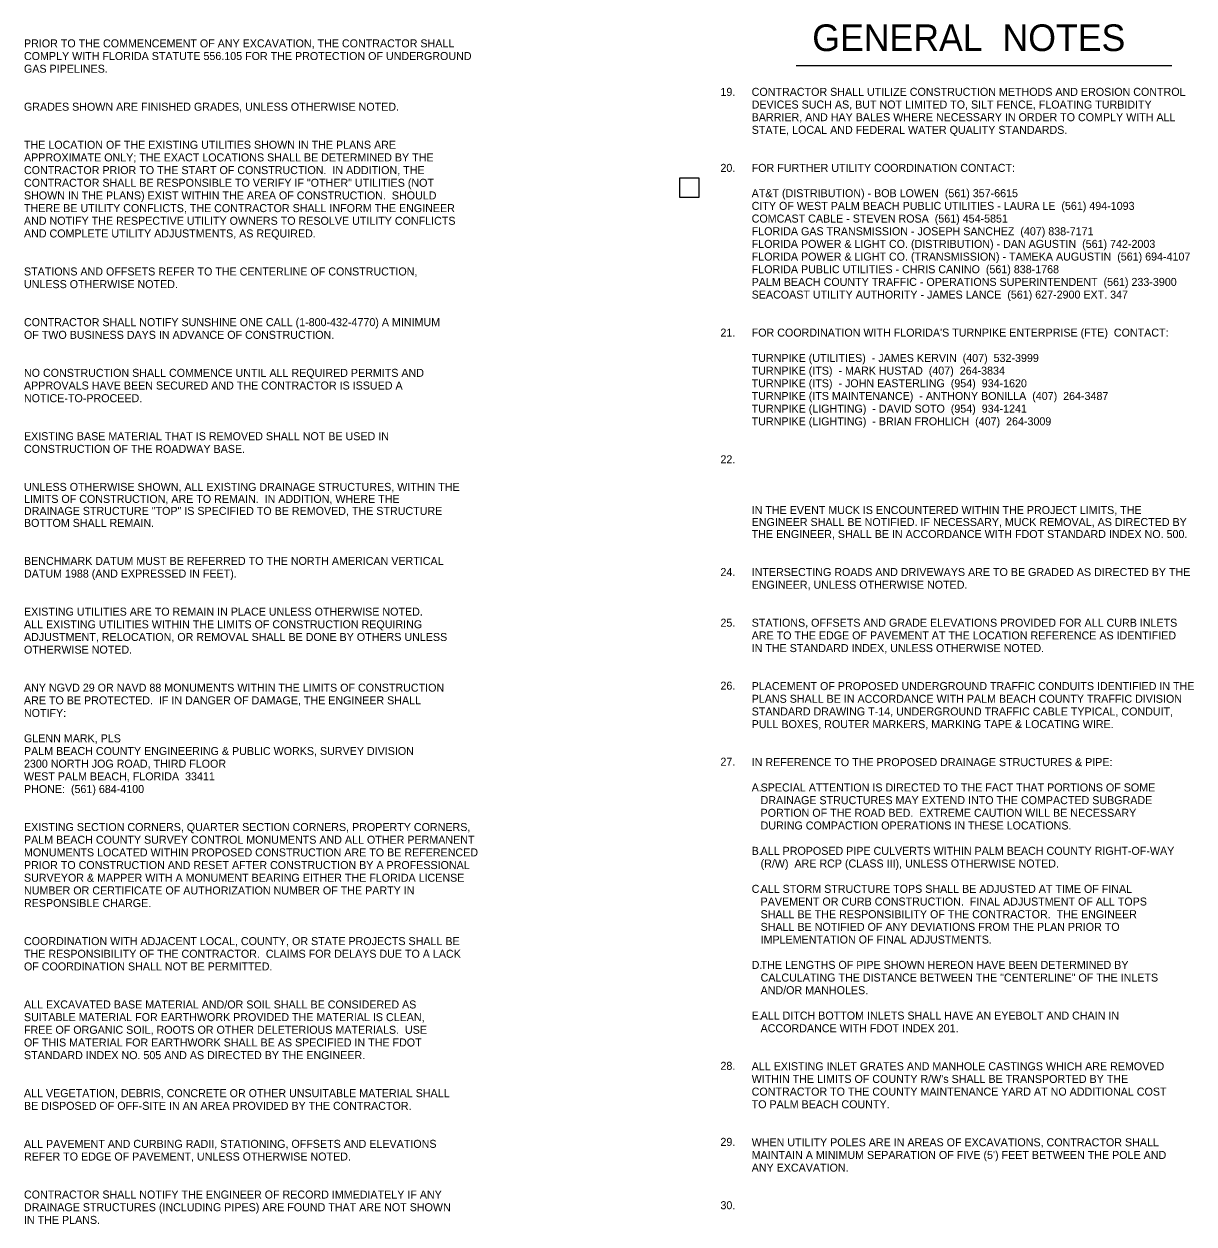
# Model space of a CAD drawing. Extents: x 783907 to 784590, y 832093 to 832609.
# Drawn here: x 784196.7 to 784284.5, y 832519 to 832609 of the extents above; entities that cross this region are included whole.
import ezdxf

# ---------------------------------------------------------------- set-up
doc = ezdxf.new("R2010")
doc.units = 0
doc.layers.add('Default', color=7, linetype='Continuous')

msp = doc.modelspace()

# ---------------------------------------------------------------- linework, layer by layer
at = {"layer": 'Default'}
msp.add_line((784254.603, 832605.859), (784282.795, 832605.859), dxfattribs=at)
msp.add_lwpolyline([(784245.898, 832597.448), (784247.319, 832597.448), (784247.319, 832595.971), (784245.898, 832595.971)], close=True, dxfattribs=at)

# ---------------------------------------------------------------- texts
for s, height, p in [('GENERAL  NOTES', 2, (784255.817, 832606.943)), ('PRIOR TO THE COMMENCEMENT OF ANY EXCAVATION, THE CONTRACTOR SHALL ', 0.6, (784196.695, 832607.22)), ('COMPLY WITH FLORIDA STATUTE 556.105 FOR THE PROTECTION OF UNDERGROUND', 0.6, (784196.695, 832606.27)), ('GAS PIPELINES.', 0.6, (784196.695, 832605.32)), ('19.', 0.6, (784248.932, 832603.587)), ('CONTRACTOR SHALL UTILIZE CONSTRUCTION METHODS AND EROSION CONTROL', 0.6, (784251.275, 832603.587)), ('GRADES SHOWN ARE FINISHED GRADES, UNLESS OTHERWISE NOTED.', 0.6, (784196.695, 832602.47)), ('DEVICES SUCH AS, BUT NOT LIMITED TO, SILT FENCE, FLOATING TURBIDITY', 0.6, (784251.275, 832602.637)), ('BARRIER, AND HAY BALES WHERE NECESSARY IN ORDER TO COMPLY WITH ALL', 0.6, (784251.275, 832601.687)), ('STATE, LOCAL AND FEDERAL WATER QUALITY STANDARDS.', 0.6, (784251.275, 832600.737)), ('THE LOCATION OF THE EXISTING UTILITIES SHOWN IN THE PLANS ARE', 0.6, (784196.695, 832599.62)), ('APPROXIMATE ONLY; THE EXACT LOCATIONS SHALL BE DETERMINED BY THE', 0.6, (784196.695, 832598.67)), ('CONTRACTOR PRIOR TO THE START OF CONSTRUCTION.  IN ADDITION, THE', 0.6, (784196.695, 832597.72)), ('20.', 0.6, (784248.932, 832597.887)), ('FOR FURTHER UTILITY COORDINATION CONTACT:', 0.6, (784251.275, 832597.887)), ('CONTRACTOR SHALL BE RESPONSIBLE TO VERIFY IF "OTHER" UTILITIES (NOT', 0.6, (784196.695, 832596.77)), ('SHOWN IN THE PLANS) EXIST WITHIN THE AREA OF CONSTRUCTION.  SHOULD', 0.6, (784196.695, 832595.82)), ('AT&T (DISTRIBUTION) - BOB LOWEN  (561) 357-6615 ', 0.6, (784251.275, 832595.987)), ('THERE BE UTILITY CONFLICTS, THE CONTRACTOR SHALL INFORM THE ENGINEER', 0.6, (784196.695, 832594.87)), ('CITY OF WEST PALM BEACH PUBLIC UTILITIES - LAURA LE  (561) 494-1093 ', 0.6, (784251.275, 832595.037)), ('AND NOTIFY THE RESPECTIVE UTILITY OWNERS TO RESOLVE UTILITY CONFLICTS', 0.6, (784196.695, 832593.92)), ('COMCAST CABLE - STEVEN ROSA  (561) 454-5851', 0.6, (784251.275, 832594.087)), ('AND COMPLETE UTILITY ADJUSTMENTS, AS REQUIRED.', 0.6, (784196.695, 832592.97)), ('FLORIDA GAS TRANSMISSION - JOSEPH SANCHEZ  (407) 838-7171', 0.6, (784251.275, 832593.137)), ('FLORIDA POWER & LIGHT CO. (DISTRIBUTION) - DAN AGUSTIN  (561) 742-2003', 0.6, (784251.275, 832592.187)), ('FLORIDA POWER & LIGHT CO. (TRANSMISSION) - TAMEKA AUGUSTIN  (561) 694-4107', 0.6, (784251.275, 832591.237)), ('STATIONS AND OFFSETS REFER TO THE CENTERLINE OF CONSTRUCTION,', 0.6, (784196.695, 832590.12)), ('FLORIDA PUBLIC UTILITIES - CHRIS CANINO  (561) 838-1768', 0.6, (784251.275, 832590.287)), ('UNLESS OTHERWISE NOTED.', 0.6, (784196.695, 832589.17)), ('PALM BEACH COUNTY TRAFFIC - OPERATIONS SUPERINTENDENT  (561) 233-3900', 0.6, (784251.275, 832589.337)), ('SEACOAST UTILITY AUTHORITY - JAMES LANCE  (561) 627-2900 EXT. 347', 0.6, (784251.275, 832588.387)), ('CONTRACTOR SHALL NOTIFY SUNSHINE ONE CALL (1-800-432-4770) A MINIMUM', 0.6, (784196.695, 832586.32)), ('OF TWO BUSINESS DAYS IN ADVANCE OF CONSTRUCTION.', 0.6, (784196.695, 832585.37)), ('21.', 0.6, (784248.932, 832585.537)), ("FOR COORDINATION WITH FLORIDA'S TURNPIKE ENTERPRISE (FTE)  CONTACT:", 0.6, (784251.275, 832585.537)), ('TURNPIKE (UTILITIES)  - JAMES KERVIN  (407)  532-3999', 0.6, (784251.275, 832583.637)), ('TURNPIKE (ITS)  - MARK HUSTAD  (407)  264-3834', 0.6, (784251.275, 832582.687)), ('NO CONSTRUCTION SHALL COMMENCE UNTIL ALL REQUIRED PERMITS AND ', 0.6, (784196.695, 832582.52)), ('TURNPIKE (ITS)  - JOHN EASTERLING  (954)  934-1620', 0.6, (784251.275, 832581.737)), ('APPROVALS HAVE BEEN SECURED AND THE CONTRACTOR IS ISSUED A', 0.6, (784196.695, 832581.57)), ('NOTICE-TO-PROCEED.', 0.6, (784196.695, 832580.62)), ('TURNPIKE (ITS MAINTENANCE)  - ANTHONY BONILLA  (407)  264-3487', 0.6, (784251.275, 832580.787)), ('TURNPIKE (LIGHTING)  - DAVID SOTO  (954)  934-1241', 0.6, (784251.275, 832579.837)), ('TURNPIKE (LIGHTING)  - BRIAN FROHLICH  (407)  264-3009', 0.6, (784251.275, 832578.887)), ('EXISTING BASE MATERIAL THAT IS REMOVED SHALL NOT BE USED IN', 0.6, (784196.695, 832577.77)), ('CONSTRUCTION OF THE ROADWAY BASE.', 0.6, (784196.695, 832576.82)), ('22.', 0.6, (784248.932, 832576.037)), ('UNLESS OTHERWISE SHOWN, ALL EXISTING DRAINAGE STRUCTURES, WITHIN THE', 0.6, (784196.695, 832573.97)), ('LIMITS OF CONSTRUCTION, ARE TO REMAIN.  IN ADDITION, WHERE THE', 0.6, (784196.695, 832573.07)), ('DRAINAGE STRUCTURE "TOP" IS SPECIFIED TO BE REMOVED, THE STRUCTURE', 0.6, (784196.695, 832572.17)), ('IN THE EVENT MUCK IS ENCOUNTERED WITHIN THE PROJECT LIMITS, THE', 0.6, (784251.275, 832572.237)), ('BOTTOM SHALL REMAIN.', 0.6, (784196.695, 832571.27)), ('ENGINEER SHALL BE NOTIFIED. IF NECESSARY, MUCK REMOVAL, AS DIRECTED BY', 0.6, (784251.275, 832571.337)), ('THE ENGINEER, SHALL BE IN ACCORDANCE WITH FDOT STANDARD INDEX NO. 500. ', 0.6, (784251.275, 832570.437)), ('BENCHMARK DATUM MUST BE REFERRED TO THE NORTH AMERICAN VERTICAL', 0.6, (784196.695, 832568.42)), ('DATUM 1988 (AND EXPRESSED IN FEET).', 0.6, (784196.695, 832567.47)), ('24.', 0.6, (784248.932, 832567.587)), ('INTERSECTING ROADS AND DRIVEWAYS ARE TO BE GRADED AS DIRECTED BY THE', 0.6, (784251.275, 832567.587)), ('ENGINEER, UNLESS OTHERWISE NOTED.', 0.6, (784251.275, 832566.637)), ('EXISTING UTILITIES ARE TO REMAIN IN PLACE UNLESS OTHERWISE NOTED.  ', 0.6, (784196.695, 832564.62)), ('25.', 0.6, (784248.932, 832563.787)), ('STATIONS, OFFSETS AND GRADE ELEVATIONS PROVIDED FOR ALL CURB INLETS', 0.6, (784251.275, 832563.787)), ('ALL EXISTING UTILITIES WITHIN THE LIMITS OF CONSTRUCTION REQUIRING', 0.6, (784196.695, 832563.67)), ('ARE TO THE EDGE OF PAVEMENT AT THE LOCATION REFERENCE AS IDENTIFIED', 0.6, (784251.275, 832562.837)), ('ADJUSTMENT, RELOCATION, OR REMOVAL SHALL BE DONE BY OTHERS UNLESS', 0.6, (784196.695, 832562.72)), ('OTHERWISE NOTED.', 0.6, (784196.695, 832561.77)), ('IN THE STANDARD INDEX, UNLESS OTHERWISE NOTED.', 0.6, (784251.275, 832561.887)), ('ANY NGVD 29 OR NAVD 88 MONUMENTS WITHIN THE LIMITS OF CONSTRUCTION ', 0.6, (784196.695, 832558.92)), ('26.', 0.6, (784248.932, 832559.069)), ('PLACEMENT OF PROPOSED UNDERGROUND TRAFFIC CONDUITS IDENTIFIED IN THE ', 0.6, (784251.275, 832559.037)), ('ARE TO BE PROTECTED.  IF IN DANGER OF DAMAGE, THE ENGINEER SHALL ', 0.6, (784196.695, 832557.97)), ('PLANS SHALL BE IN ACCORDANCE WITH PALM BEACH COUNTY TRAFFIC DIVISION', 0.6, (784251.275, 832558.087)), ('NOTIFY:', 0.6, (784196.695, 832557.02)), ('STANDARD DRAWING T-14, UNDERGROUND TRAFFIC CABLE TYPICAL, CONDUIT, ', 0.6, (784251.275, 832557.137)), ('PULL BOXES, ROUTER MARKERS, MARKING TAPE & LOCATING WIRE.', 0.6, (784251.275, 832556.187)), ('GLENN MARK, PLS', 0.6, (784196.695, 832555.12)), ('PALM BEACH COUNTY ENGINEERING & PUBLIC WORKS, SURVEY DIVISION', 0.6, (784196.695, 832554.17)), ('2300 NORTH JOG ROAD, THIRD FLOOR ', 0.6, (784196.695, 832553.22)), ('27.', 0.6, (784248.932, 832553.369)), ('IN REFERENCE TO THE PROPOSED DRAINAGE STRUCTURES & PIPE:', 0.6, (784251.275, 832553.337)), ('WEST PALM BEACH, FLORIDA  33411', 0.6, (784196.695, 832552.27)), ('PHONE:  (561) 684-4100', 0.6, (784196.695, 832551.32)), ('A.', 0.6, (784251.275, 832551.437)), ('   SPECIAL ATTENTION IS DIRECTED TO THE FACT THAT PORTIONS OF SOME', 0.6, (784251.275, 832551.437)), ('   DRAINAGE STRUCTURES MAY EXTEND INTO THE COMPACTED SUBGRADE', 0.6, (784251.275, 832550.487)), ('   PORTION OF THE ROAD BED.  EXTREME CAUTION WILL BE NECESSARY', 0.6, (784251.275, 832549.537)), ('EXISTING SECTION CORNERS, QUARTER SECTION CORNERS, PROPERTY CORNERS,', 0.6, (784196.695, 832548.47)), ('   DURING COMPACTION OPERATIONS IN THESE LOCATIONS.', 0.6, (784251.275, 832548.587)), ('PALM BEACH COUNTY SURVEY CONTROL MONUMENTS AND ALL OTHER PERMANENT', 0.6, (784196.695, 832547.52)), ('B.', 0.6, (784251.275, 832546.687)), ('   ALL PROPOSED PIPE CULVERTS WITHIN PALM BEACH COUNTY RIGHT-OF-WAY', 0.6, (784251.275, 832546.687)), ('MONUMENTS LOCATED WITHIN PROPOSED CONSTRUCTION ARE TO BE REFERENCED', 0.6, (784196.695, 832546.57)), ('   (R/W)  ARE RCP (CLASS III), UNLESS OTHERWISE NOTED.', 0.6, (784251.275, 832545.737)), ('PRIOR TO CONSTRUCTION AND RESET AFTER CONSTRUCTION BY A PROFESSIONAL', 0.6, (784196.695, 832545.62)), ('SURVEYOR & MAPPER WITH A MONUMENT BEARING EITHER THE FLORIDA LICENSE', 0.6, (784196.695, 832544.67)), ('NUMBER OR CERTIFICATE OF AUTHORIZATION NUMBER OF THE PARTY IN', 0.6, (784196.695, 832543.72)), ('C.', 0.6, (784251.275, 832543.837)), ('   ALL STORM STRUCTURE TOPS SHALL BE ADJUSTED AT TIME OF FINAL', 0.6, (784251.275, 832543.837)), ('RESPONSIBLE CHARGE.', 0.6, (784196.695, 832542.77)), ('   PAVEMENT OR CURB CONSTRUCTION.  FINAL ADJUSTMENT OF ALL TOPS', 0.6, (784251.275, 832542.887)), ('   SHALL BE THE RESPONSIBILITY OF THE CONTRACTOR.  THE ENGINEER', 0.6, (784251.275, 832541.937)), ('   SHALL BE NOTIFIED OF ANY DEVIATIONS FROM THE PLAN PRIOR TO ', 0.6, (784251.275, 832540.987)), ('COORDINATION WITH ADJACENT LOCAL, COUNTY, OR STATE PROJECTS SHALL BE', 0.6, (784196.695, 832539.92)), ('   IMPLEMENTATION OF FINAL ADJUSTMENTS.', 0.6, (784251.275, 832540.037)), ('THE RESPONSIBILITY OF THE CONTRACTOR.  CLAIMS FOR DELAYS DUE TO A LACK ', 0.6, (784196.695, 832538.97)), ('OF COORDINATION SHALL NOT BE PERMITTED.', 0.6, (784196.695, 832538.02)), ('D.', 0.6, (784251.275, 832538.137)), ('   THE LENGTHS OF PIPE SHOWN HEREON HAVE BEEN DETERMINED BY', 0.6, (784251.275, 832538.137)), ('   CALCULATING THE DISTANCE BETWEEN THE "CENTERLINE" OF THE INLETS', 0.6, (784251.275, 832537.187)), ('   AND/OR MANHOLES.', 0.6, (784251.275, 832536.237)), ('ALL EXCAVATED BASE MATERIAL AND/OR SOIL SHALL BE CONSIDERED AS ', 0.6, (784196.695, 832535.17)), ('SUITABLE MATERIAL FOR EARTHWORK PROVIDED THE MATERIAL IS CLEAN, ', 0.6, (784196.695, 832534.22)), ('E.', 0.6, (784251.275, 832534.337)), ('   ALL DITCH BOTTOM INLETS SHALL HAVE AN EYEBOLT AND CHAIN IN', 0.6, (784251.275, 832534.337)), ('FREE OF ORGANIC SOIL, ROOTS OR OTHER DELETERIOUS MATERIALS.  USE ', 0.6, (784196.695, 832533.27)), ('   ACCORDANCE WITH FDOT INDEX 201.', 0.6, (784251.275, 832533.387)), ('OF THIS MATERIAL FOR EARTHWORK SHALL BE AS SPECIFIED IN THE FDOT ', 0.6, (784196.695, 832532.32)), ('STANDARD INDEX NO. 505 AND AS DIRECTED BY THE ENGINEER.', 0.6, (784196.695, 832531.37)), ('28.', 0.6, (784248.932, 832530.57)), ('ALL EXISTING INLET GRATES AND MANHOLE CASTINGS WHICH ARE REMOVED', 0.6, (784251.275, 832530.537)), ("WITHIN THE LIMITS OF COUNTY R/W's SHALL BE TRANSPORTED BY THE", 0.6, (784251.275, 832529.587)), ('CONTRACTOR TO THE COUNTY MAINTENANCE YARD AT NO ADDITIONAL COST', 0.6, (784251.275, 832528.637)), ('ALL VEGETATION, DEBRIS, CONCRETE OR OTHER UNSUITABLE MATERIAL SHALL ', 0.6, (784196.695, 832528.52)), ('BE DISPOSED OF OFF-SITE IN AN AREA PROVIDED BY THE CONTRACTOR.', 0.6, (784196.695, 832527.57)), ('TO PALM BEACH COUNTY.', 0.6, (784251.275, 832527.687)), ('ALL PAVEMENT AND CURBING RADII, STATIONING, OFFSETS AND ELEVATIONS ', 0.6, (784196.695, 832524.72)), ('29.', 0.6, (784248.932, 832524.87)), ('WHEN UTILITY POLES ARE IN AREAS OF EXCAVATIONS, CONTRACTOR SHALL', 0.6, (784251.275, 832524.837)), ('REFER TO EDGE OF PAVEMENT, UNLESS OTHERWISE NOTED.', 0.6, (784196.695, 832523.77)), ("MAINTAIN A MINIMUM SEPARATION OF FIVE (5') FEET BETWEEN THE POLE AND", 0.6, (784251.275, 832523.887)), ('ANY EXCAVATION.', 0.6, (784251.275, 832522.937)), ('CONTRACTOR SHALL NOTIFY THE ENGINEER OF RECORD IMMEDIATELY IF ANY', 0.6, (784196.695, 832520.92)), ('DRAINAGE STRUCTURES (INCLUDING PIPES) ARE FOUND THAT ARE NOT SHOWN', 0.6, (784196.695, 832519.97)), ('30.', 0.6, (784248.932, 832520.12)), ('IN THE PLANS.', 0.6, (784196.695, 832519.02))]:
    msp.add_text(s, height=height, dxfattribs=at).set_placement(p)

doc.saveas('drawing.dxf')
